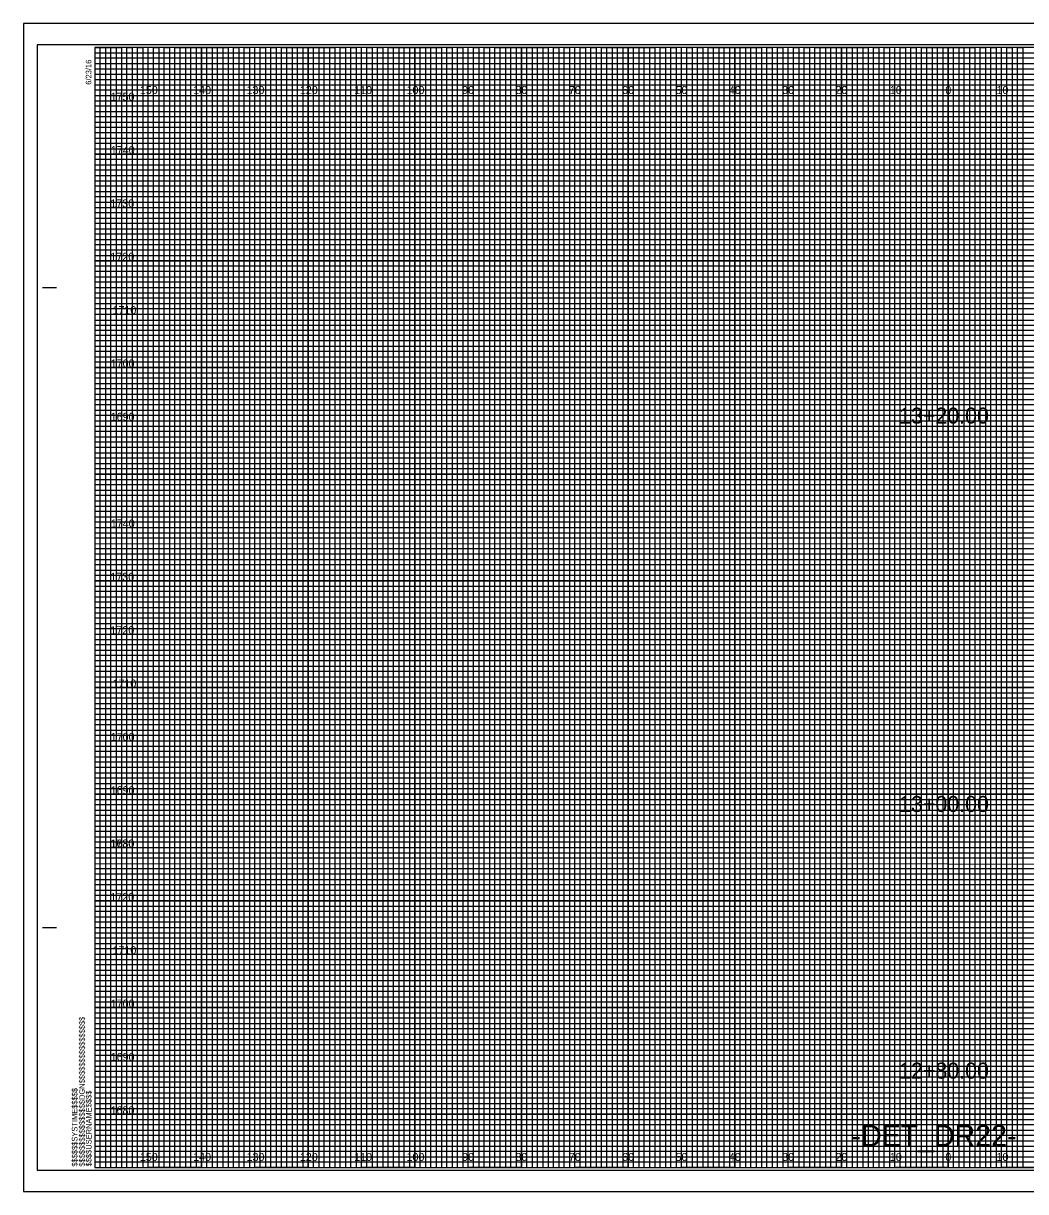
# Model space of a CAD drawing. Extents: x -13 to 323, y -5 to 1314.
# Drawn here: x -13.4 to 174.5, y 655.5 to 874.5 of the extents above; entities that cross this region are included whole.
import ezdxf

# ---------------------------------------------------------------- set-up
doc = ezdxf.new("R2010")
doc.units = 0
for name, color, linetype in [('Prop Horizontal Alignment', 7, 'Continuous'), ('Prop XS Alignment Label', 7, 'Continuous'), ('Raster_Level_0', 7, 'Continuous'), ('Scratch_Level_3', 7, 'Continuous'), ('Sheet Cross Section CELL', 7, 'Continuous'), ('Sheet Cross Section Grid Major CELL', 7, 'Continuous'), ('Sheet Cross Section Grid Middle CELL', 7, 'Continuous'), ('Sheet Cross Section Grid Minor 1 CELL', 7, 'Continuous'), ('Sheet Cross Section Grid Minor 2 CELL', 7, 'Continuous'), ('Sheet Cutting Line CELL', 7, 'Continuous'), ('Sheet DOT Grid CELL', 7, 'Continuous'), ('Sheet Plot Border Inside CELL', 7, 'Continuous'), ('Sheet Plot Border Outside CELL', 7, 'Continuous')]:
    doc.layers.add(name, color=color, linetype=linetype)

msp = doc.modelspace()

# ---------------------------------------------------------------- linework, layer by layer
at = {"layer": 'Sheet Cross Section CELL'}
for p, q in [((-9.8, 825), (-7.3, 825)), ((-9.7, 825), (-7.2, 825)), ((-9.8, 705), (-7.3, 705)), ((-9.7, 705), (-7.2, 705)), ((0, 660), (0, 660)), ((0, 660), (0, 660)), ((0, 660), (0, 660)), ((0, 660), (0, 660)), ((0, 660), (0, 660)), ((0, 660), (0, 660)), ((0, 660), (0, 660))]:
    msp.add_line(p, q, dxfattribs=at)
msp.add_lwpolyline([(320, 870), (0, 870), (0, 660), (320, 660)], close=True, dxfattribs=at)
at = {"layer": 'Sheet Cross Section Grid Major CELL'}
for p, q in [((10, 870), (0, 870)), ((10, 660), (10, 870)), ((30, 870), (20, 870)), ((20, 870), (20, 660)), ((30, 660), (30, 870)), ((50, 870), (40, 870)), ((40, 870), (40, 660)), ((50, 660), (50, 870)), ((70, 870), (60, 870)), ((60, 870), (60, 660)), ((70, 660), (70, 870)), ((90, 870), (80, 870)), ((80, 870), (80, 660)), ((90, 660), (90, 870)), ((110, 870), (100, 870)), ((100, 870), (100, 660)), ((110, 660), (110, 870)), ((130, 870), (120, 870)), ((120, 870), (120, 660)), ((130, 660), (130, 870)), ((150, 870), (140, 870)), ((140, 870), (140, 660)), ((150, 660), (150, 870)), ((170, 870), (160, 870)), ((160, 870), (160, 660)), ((170, 660), (170, 870)), ((20, 660), (10, 660)), ((40, 660), (30, 660)), ((60, 660), (50, 660)), ((80, 660), (70, 660)), ((100, 660), (90, 660)), ((120, 660), (110, 660)), ((140, 660), (130, 660)), ((160, 660), (150, 660)), ((180, 660), (170, 660))]:
    msp.add_line(p, q, dxfattribs=at)
for points in [[(0, 860), (320, 860), (320, 850), (0, 850)], [(0, 840), (320, 840), (320, 830), (0, 830)], [(0, 820), (320, 820), (320, 810), (0, 810)], [(0, 800), (320, 800), (320, 790), (0, 790)], [(0, 780), (320, 780), (320, 770), (0, 770)], [(0, 760), (320, 760), (320, 750), (0, 750)], [(0, 740), (320, 740), (320, 730), (0, 730)], [(0, 720), (320, 720), (320, 710), (0, 710)], [(0, 700), (320, 700), (320, 690), (0, 690)], [(0, 680), (320, 680), (320, 670), (0, 670)]]:
    msp.add_lwpolyline(points, dxfattribs=at)
at = {"layer": 'Sheet Cross Section Grid Middle CELL'}
for points in [[(0, 870), (5, 870), (5, 660), (15, 660), (15, 870), (25, 870), (25, 660), (35, 660), (35, 870), (45, 870), (45, 660), (55, 660), (55, 870), (65, 870), (65, 660), (75, 660), (75, 870), (85, 870), (85, 660), (95, 660), (95, 870), (105, 870), (105, 660), (115, 660), (115, 870), (125, 870), (125, 660), (135, 660), (135, 870), (145, 870), (145, 660), (155, 660), (155, 870), (165, 870), (165, 660), (175, 660)], [(0, 865), (275, 865)], [(0, 845), (320, 845), (320, 855), (0, 855)], [(0, 825), (320, 825), (320, 835), (0, 835)], [(0, 805), (320, 805), (320, 815), (0, 815)], [(0, 785), (320, 785), (320, 795), (0, 795)], [(0, 765), (320, 765), (320, 775), (0, 775)], [(0, 745), (320, 745), (320, 755), (0, 755)], [(0, 725), (320, 725), (320, 735), (0, 735)], [(0, 705), (320, 705), (320, 715), (0, 715)], [(0, 685), (320, 685), (320, 695), (0, 695)], [(0, 665), (320, 665), (320, 675), (0, 675)]]:
    msp.add_lwpolyline(points, dxfattribs=at)
at = {"layer": 'Sheet Cross Section Grid Minor 1 CELL'}
for p, q in [((0, 869), (260, 869)), ((260, 867.98), (0, 867.98)), ((0, 867.98), (0, 867)), ((0, 867), (260, 867)), ((260, 865.89), (0, 865.89)), ((0, 865.89), (0, 864)), ((0, 864), (320, 864))]:
    msp.add_line(p, q, dxfattribs=at)
for points in [[(0, 863), (270, 863), (320, 863), (320, 862), (0, 862)], [(0, 861), (320, 861), (320, 859), (0, 859)], [(0, 858), (320, 858), (320, 857), (0, 856.98)], [(0, 856), (320, 856), (320, 854), (0, 854)], [(0, 853), (320, 853), (320, 852), (0, 852)], [(0, 851), (320, 851), (320, 849), (0, 849)], [(0, 848), (320, 848), (320, 847), (0, 847)], [(0, 846), (320, 846), (320, 844), (0, 844)], [(0, 843), (320, 843), (320, 842), (0, 842)], [(0, 841), (320, 841), (320, 839), (0, 839)], [(0, 838), (320, 838), (320, 837), (0, 837)], [(0, 836), (320, 836), (320, 833.95), (320, 833), (320, 832), (0, 832)], [(0, 834), (320, 834), (320, 833), (0, 833)], [(0, 831), (320, 831), (320, 829), (0, 829.03)], [(0, 829.03), (320, 829), (320, 828), (0, 828)], [(0, 827), (320, 827), (320, 826), (0, 826)], [(0, 824), (320, 824), (320, 823), (0, 823)], [(0, 822), (320, 822), (320, 821), (0, 821)], [(-0.07, 818.89), (320, 818.89), (320, 817.88), (-0.07, 817.88)], [(0, 817), (320, 817), (320, 816), (0, 816)], [(0, 814), (320, 814), (320, 813), (0, 813)], [(0, 812), (320, 812), (320, 811), (0, 811)], [(0, 809), (320, 809), (320, 808), (0, 808)], [(0, 807), (320, 807), (320, 806), (0, 806)], [(0, 804), (320, 804), (320, 803), (0, 803)], [(0, 802), (320, 802), (320, 801), (0, 801)], [(0, 799), (320, 799), (319.99, 797.98), (0, 798)], [(0, 797), (320, 797), (320, 796), (0, 796)], [(0, 794), (320, 794), (320, 793), (0, 793)], [(0, 792), (320, 792), (320, 791), (0, 791)], [(0, 789), (320, 789), (320, 788), (0, 788)], [(0, 787), (320, 787), (320, 786), (0, 786)], [(0, 784), (320, 784), (320, 783), (0, 783)], [(0, 782), (320, 782), (320, 781), (0, 781)], [(0, 779), (320, 779), (320, 778), (0, 778)], [(0, 776.99), (320.07, 776.91), (320, 776), (0, 776)], [(0, 774), (320, 774), (320, 773), (0, 773)], [(0, 772), (320, 772), (320, 771), (0, 771)], [(0, 769), (320, 769), (320, 768), (0, 768)], [(0, 767), (320, 767), (320, 766), (0, 766)], [(0, 764), (320, 764), (320, 763), (0, 763)], [(0, 762), (320, 762), (320, 761), (0, 761)], [(0, 759), (320, 759), (320, 758), (0, 758)], [(0, 757), (320, 757), (320, 756), (0, 756)], [(0, 754), (320, 754), (320, 753), (0, 753)], [(0, 752), (320, 752), (320, 751), (0, 751)], [(0, 749), (320, 749), (320, 748), (0, 748)], [(0, 747), (320, 747), (320, 746), (0, 746)], [(0, 744), (320, 744), (320, 743), (0, 743)], [(0, 742), (320, 742), (320, 741), (0, 741)], [(0, 739), (320, 739), (319.99, 737.98), (0, 738)], [(0, 737), (320, 737), (320, 736), (0, 736)], [(0, 734), (320, 734), (320, 733), (0, 733)], [(0, 732), (320, 732), (320, 731), (0, 731)], [(0, 729), (320, 729), (320, 728), (0, 728)], [(0, 727), (320, 727), (320, 726), (0, 726)], [(0, 724), (320, 724), (320, 723), (0, 723)], [(0, 722), (320, 722), (320, 721), (0, 721)], [(0, 719), (320, 719), (320, 718), (0, 718)], [(0, 716.99), (320.07, 716.91), (320, 716), (0, 716)], [(0, 714), (320, 714), (320, 713), (0, 713)], [(0, 712), (320, 712), (320, 711), (0, 711)], [(0, 709), (320, 709), (320, 708), (0, 708)], [(0, 707), (320, 707), (320, 706), (0, 706)], [(0, 704), (320, 704), (320, 703), (0, 703)], [(0, 702), (320, 702), (320, 701), (0, 701)], [(0, 699), (320, 699), (320, 698), (0, 698)], [(0, 697), (320, 697), (320, 696), (0, 696)], [(0, 694), (320, 694), (320, 693), (0, 693)], [(0, 692), (320, 692), (320, 691), (0, 691)], [(0, 689), (320, 689), (320, 688), (0, 688)], [(0, 687), (320, 687), (320, 686), (0, 686)], [(0, 684), (320, 684), (320, 683), (0, 683)], [(0, 682), (320, 682), (320, 681), (0, 681)], [(0, 679), (320, 679), (320, 678), (0, 678)], [(0, 677), (320, 677), (320, 676), (0, 676)], [(0, 674), (320, 674), (320, 673), (0, 673)], [(0, 672), (320, 672), (320, 671), (0, 671)], [(0, 669), (320, 669), (320, 668), (0, 668)], [(0, 667), (320, 667), (320, 666), (0, 666)], [(0, 664), (320, 664), (320, 663), (0, 663)], [(0, 662), (320, 662), (320, 661), (0, 661)]]:
    msp.add_lwpolyline(points, dxfattribs=at)
at = {"layer": 'Sheet Cross Section Grid Minor 2 CELL'}
for points in [[(0, 660), (1, 660), (1, 870), (2, 870), (2, 660)], [(2, 660), (3, 660), (3, 870), (4, 870), (4, 660)], [(5, 660), (6, 660), (6, 870), (7, 870), (7, 660)], [(7, 660), (8, 660), (8, 870), (9, 870), (9, 660)], [(10, 660), (11, 660), (11, 870), (12, 870), (12, 660)], [(12, 660), (13, 660), (13, 870), (14, 870), (14, 660)], [(15, 660), (16, 660), (16, 870), (17, 870), (17, 660)], [(17, 660), (18, 660), (18, 870), (19, 870), (19, 660)], [(20, 660), (21, 660), (21, 870), (22, 870), (22, 660)], [(22, 660), (23, 660), (23, 870), (24, 870), (24, 660)], [(25, 660), (26, 660), (26, 870), (27, 870), (27, 660)], [(27, 660), (28, 660), (28, 870), (29, 870), (29, 660)], [(30, 660), (31, 660), (31, 870), (32, 870), (32, 660)], [(32, 660), (33, 660), (33, 870), (34, 870), (34, 660)], [(35, 660), (36, 660), (36, 870), (37, 870), (37, 660)], [(37, 660), (38, 660), (38, 870), (39, 870), (39, 660)], [(40, 660), (41, 660), (41, 870), (42, 870), (42, 660)], [(42, 660), (43, 660), (43, 870), (44, 870), (44, 660)], [(45, 660), (46, 660), (46, 870), (47, 870), (47, 660)], [(47, 660), (48, 660), (48, 870), (49, 870), (49, 660)], [(50, 660), (51, 660), (51, 870), (52, 870), (52, 660)], [(52, 660), (53, 660), (53, 870), (54, 870), (54, 660)], [(55, 660), (56, 660), (56, 870), (57, 870), (57, 660)], [(57, 660), (58, 660), (58, 870), (59, 870), (59, 660)], [(60, 660), (61, 660), (61, 870), (62, 870), (62, 660)], [(62, 660), (63, 660), (63, 870), (64, 870), (64, 660)], [(65, 660), (66, 660), (66, 870), (67, 870), (67, 660)], [(67, 660), (68, 660), (68, 870), (69, 870), (69, 660)], [(70, 660), (71, 660), (71, 870), (72, 870), (72, 660)], [(72, 660), (73, 660), (73, 870), (74, 870), (74, 660)], [(75, 660), (76, 660), (76, 870), (77, 870), (77, 660)], [(77, 660), (78, 660), (78, 870), (79, 870), (79, 660)], [(80, 660), (81, 660), (81, 870), (82, 870), (82, 660)], [(82, 660), (83, 660), (83, 870), (84, 870), (84, 660)], [(85, 660), (86, 660), (86, 870), (87, 870), (87, 660)], [(87, 660), (88, 660), (88, 870), (89, 870), (89, 660)], [(90, 660), (91, 660), (91, 870), (92, 870), (92, 660)], [(92, 660), (93, 660), (93, 870), (94, 870), (94, 660)], [(95, 660), (96, 660), (96, 870), (97, 870), (97, 660)], [(97, 660), (98, 660), (98, 870), (99, 870), (99, 660)], [(100, 660), (101, 660), (101, 870), (102, 870), (102, 660)], [(102, 660), (103, 660), (103, 870), (104, 870), (104, 660)], [(105, 660), (106, 660), (106, 870), (107, 870), (107, 660)], [(107, 660), (108, 660), (108, 870), (109, 870), (109, 660)], [(110, 660), (111, 660), (111, 870), (112, 870), (112, 660)], [(112, 660), (113, 660), (113, 870), (114, 870), (114, 660)], [(115, 660), (116, 660), (116, 870), (117, 870), (117, 660)], [(117, 660), (118, 660), (118, 870), (119, 870), (119, 660)], [(120, 660), (121, 660), (121, 870), (122, 870), (122, 660)], [(122, 660), (123, 660), (123, 870), (124, 870), (124, 660)], [(125, 660), (126, 660), (126, 870), (127, 870), (127, 660)], [(127, 660), (128, 660), (128, 870), (129, 870), (129, 660)], [(130, 660), (131, 660), (131, 870), (132, 870), (132, 660)], [(132, 660), (133, 660), (133, 870), (134, 870), (134, 660)], [(135, 660), (136, 660), (136, 870), (137, 870), (137, 660)], [(137, 660), (138, 660), (138, 870), (139, 870), (139, 660)], [(140, 660), (141, 660), (141, 870), (142, 870), (142, 660)], [(142, 660), (143, 660), (143, 870), (144, 870), (144, 660)], [(145, 660), (146, 660), (146, 870), (147, 870), (147, 660)], [(147, 660), (148, 660), (148, 870), (149, 870), (149, 660)], [(150, 660), (151, 660), (151, 870), (152, 870), (152, 660)], [(152, 660), (153, 660), (153, 870), (154, 870), (154, 660)], [(155, 660), (156, 660), (156, 870), (157, 870), (157, 660)], [(157, 660), (158, 660), (158, 870), (159, 870), (159, 660)], [(160, 660), (161, 660), (161, 870), (162, 870), (162, 660)], [(162, 660), (163, 660), (163, 870), (164, 870), (164, 660)], [(165, 660), (166, 660), (166, 870), (167, 870), (167, 660)], [(167, 660), (168, 660), (168, 870), (169, 870), (169, 660)], [(170, 660), (171, 660), (171, 870), (172, 870), (172, 660)], [(172, 660), (173, 660), (173, 870), (174, 870), (174, 660)]]:
    msp.add_lwpolyline(points, dxfattribs=at)
at = {"layer": 'Sheet Cutting Line CELL'}
for p, q in [((323.3, 874.5), (-13.4, 874.5)), ((-13.4, 874.5), (-13.4, 655.5)), ((-13.4, 655.5), (323.3, 655.5))]:
    msp.add_line(p, q, dxfattribs=at)
at = {"layer": 'Sheet DOT Grid CELL'}
for p, q in [((10, 660), (10, 870)), ((20, 660), (20, 870)), ((30, 660), (30, 870)), ((40, 660), (40, 870)), ((50, 660), (50, 870)), ((60, 660), (60, 870)), ((70, 660), (70, 870)), ((80, 660), (80, 870)), ((90, 660), (90, 870)), ((100, 660), (100, 870)), ((110, 660), (110, 870)), ((120, 660), (120, 870)), ((130, 660), (130, 870)), ((140, 660), (140, 870)), ((150, 660), (150, 870)), ((160, 660), (160, 870)), ((170, 660), (170, 870)), ((0, 860), (320, 860)), ((0, 850), (320, 850)), ((0, 840), (320, 840)), ((0, 830), (320, 830)), ((0, 820), (320, 820)), ((0, 810), (320, 810)), ((0, 800), (320, 800)), ((0, 790), (320, 790)), ((0, 780), (320, 780)), ((0, 770), (320, 770)), ((0, 760), (320, 760)), ((0, 750), (320, 750)), ((0, 740), (320, 740)), ((0, 730), (320, 730)), ((0, 720), (320, 720)), ((0, 710), (320, 710)), ((0, 700), (320, 700)), ((0, 690), (320, 690)), ((0, 680), (320, 680)), ((0, 670), (320, 670))]:
    msp.add_line(p, q, dxfattribs=at)
at = {"layer": 'Sheet Plot Border Inside CELL'}
msp.add_lwpolyline([(-10.8, 659.5), (322.4, 659.5), (322.4, 870.5), (-10.8, 870.5)], close=True, dxfattribs=at)
at = {"layer": 'Sheet Plot Border Outside CELL'}
msp.add_lwpolyline([(-13.4, 655.5), (323.3, 655.5), (323.3, 874.5), (-13.4, 874.5)], close=True, dxfattribs=at)

# ---------------------------------------------------------------- texts
at = {"layer": 'Prop Horizontal Alignment'}
for s, p in [('13+20.00', (150.77, 799.47)), ('13+00.00', (150.77, 726.67)), ('12+80.00', (150.77, 676.68))]:
    msp.add_text(s, height=3, dxfattribs=at).set_placement(p)
at = {"layer": 'Prop XS Alignment Label'}
msp.add_text('-DET_DR22-', height=4, dxfattribs=at).set_placement((141.87, 664))
at = {"layer": 'Raster_Level_0'}
for s, p in [('150', (8.44, 861.25)), ('140', (18.44, 861.25)), ('130', (28.44, 861.25)), ('120', (38.44, 861.25)), ('110', (48.62, 861.25)), ('100', (58.44, 861.25)), ('90', (68.86, 861.25)), ('80', (78.86, 861.25)), ('70', (88.86, 861.25)), ('60', (98.86, 861.25)), ('50', (108.86, 861.25)), ('40', (118.86, 861.25)), ('30', (128.86, 861.25)), ('20', (138.86, 861.25)), ('10', (149.04, 861.25)), ('0', (159.45, 861.25)), ('0', (159.45, 861.25)), ('10', (169.04, 861.25)), ('150', (8.44, 661.25)), ('140', (18.44, 661.25)), ('130', (28.44, 661.25)), ('120', (38.44, 661.25)), ('110', (48.62, 661.25)), ('100', (58.44, 661.25)), ('90', (68.86, 661.25)), ('80', (78.86, 661.25)), ('70', (88.86, 661.25)), ('60', (98.86, 661.25)), ('50', (108.86, 661.25)), ('40', (118.86, 661.25)), ('30', (128.86, 661.25)), ('20', (138.86, 661.25)), ('10', (149.04, 661.25)), ('0', (159.45, 661.25)), ('0', (159.45, 661.25)), ('10', (169.04, 661.25))]:
    msp.add_text(s, height=1.5, dxfattribs=at).set_placement(p)
at = {"layer": 'Scratch_Level_3'}
for s, p in [('1750', (2.96, 860)), ('1740', (3, 850)), ('1730', (2.92, 840)), ('1720', (2.93, 830)), ('1710', (3.31, 820)), ('1700', (2.98, 810)), ('1690', (2.97, 800)), ('1740', (3, 780)), ('1730', (2.92, 770)), ('1720', (2.93, 760)), ('1710', (3.31, 750)), ('1700', (2.98, 740)), ('1690', (2.97, 730)), ('1730', (2.92, 720)), ('1680', (2.95, 720)), ('1720', (2.93, 710)), ('1710', (3.31, 700)), ('1700', (2.98, 690)), ('1690', (2.97, 680)), ('1680', (2.95, 670))]:
    msp.add_text(s, height=1.5, dxfattribs=at).set_placement(p)
at = {"layer": 'Sheet Cross Section CELL'}
for s, p in [('6/23/16', (-0.65, 863)), ('$$$$$$$$$$$$$$$$DGN$$$$$$$$$$$$$$$$', (-1.88, 660.18)), ('$$$$$$SYSTIME$$$$$', (-3.26, 660.18)), ('$$$$USERNAME$$$$', (-0.62, 660.23))]:
    msp.add_text(s, height=1.05, rotation=90, dxfattribs=at).set_placement(p)

doc.saveas('drawing.dxf')
